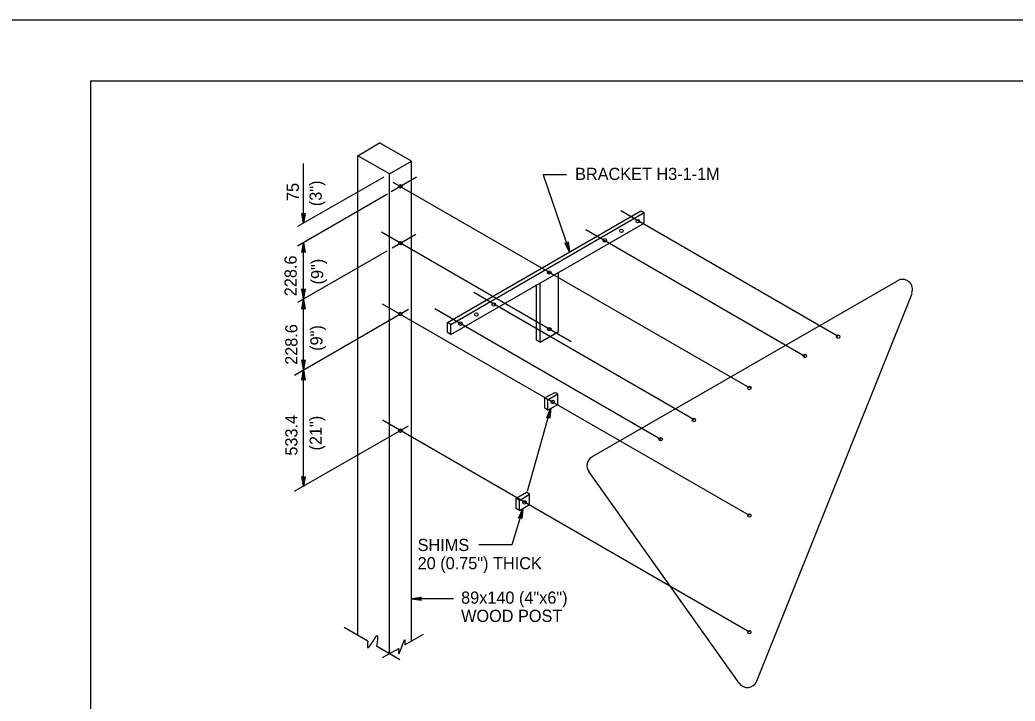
# Model space of a CAD drawing. Extents: x 649454 to 651200, y 295188 to 295782.
# Drawn here: x 650317.9 to 650563.3, y 295613.6 to 295781.6 of the extents above; entities that cross this region are included whole.
import ezdxf

# ---------------------------------------------------------------- set-up
doc = ezdxf.new("R2010")
doc.units = 0
for name, color, linetype in [('1', 7, 'Continuous'), ('2', 7, 'Continuous'), ('3', 7, 'Continuous'), ('PLT-BNDY', 7, 'Continuous')]:
    doc.layers.add(name, color=color, linetype=linetype)

msp = doc.modelspace()

# ---------------------------------------------------------------- linework, layer by layer
at = {"layer": '1'}
for q in [(651121.31, 295766.63), (650335.31, 295202.63)]:
    msp.add_line((650335.31, 295766.63), q, dxfattribs=at)
at = {"layer": '2'}
for points in [[(650452.69, 295743.39), (650446.94, 295743.39), (650453.44, 295724.39)], [(650452.94, 295726.77), (650452.81, 295726.52), (650453.44, 295724.39), (650452.94, 295726.77), (650453.06, 295726.89), (650453.44, 295724.39), (650452.56, 295726.52), (650452.44, 295726.52), (650453.44, 295724.39), (650452.31, 295726.64), (650452.44, 295726.52)], [(650447.94, 295683.64), (650448.19, 295683.64), (650448.81, 295685.89), (650447.94, 295683.64), (650447.81, 295683.52), (650448.81, 295685.89), (650448.31, 295683.64), (650448.44, 295683.52), (650448.81, 295685.89), (650448.56, 295683.39), (650448.44, 295683.52)], [(650440.94, 295658.89), (650441.19, 295658.89), (650441.94, 295661.02), (650440.94, 295658.89), (650440.81, 295658.77), (650441.94, 295661.02), (650441.44, 295658.89), (650441.56, 295658.77), (650441.94, 295661.02), (650441.69, 295658.64), (650441.56, 295658.77)], [(650416.81, 295638.52), (650416.69, 295638.77), (650414.44, 295638.89), (650416.81, 295638.52), (650416.94, 295638.52), (650414.44, 295638.89), (650416.69, 295639.02), (650416.81, 295639.14), (650414.44, 295638.89), (650416.94, 295639.27), (650416.81, 295639.14)], [(650424.81, 295638.89), (650414.44, 295638.89)]]:
    msp.add_lwpolyline(points, dxfattribs=at)
for centre, start, end in [((650535.54, 295715.15), 338.2171, 119.9923), ((650460.21, 295671.66), 119.9878, 215.3941), ((650497.3, 295619.47), 215.3991, 336.1301)]:
    msp.add_arc(centre, 2.49, start, end, dxfattribs=at)
at = {"layer": '3'}
for p, q in [((650401.19, 295748.14), (650406.56, 295751.27)), ((650414.44, 295746.77), (650406.56, 295751.27)), ((650401.19, 295629.77), (650401.19, 295748.14)), ((650409.06, 295743.64), (650401.19, 295748.14)), ((650387.81, 295731.52), (650387.81, 295746.21)), ((650409.06, 295743.64), (650414.44, 295746.77)), ((650414.44, 295628.52), (650414.44, 295746.77)), ((650409.06, 295625.39), (650409.06, 295743.64)), ((650386.44, 295730.77), (650407.69, 295742.89)), ((650409.44, 295739.27), (650415.69, 295742.89)), ((650497.81, 295690.89), (650409.94, 295741.52)), ((650386.31, 295725.89), (650408.56, 295738.77)), ((650411.69, 295740.52), (650411.69, 295740.52)), ((650423.31, 295707.02), (650471.06, 295734.52)), ((650424.19, 295706.52), (650471.81, 295734.14)), ((650519.69, 295703.52), (650466.06, 295734.52)), ((650469.69, 295734.02), (650469.69, 295734.02)), ((650471.06, 295734.52), (650471.81, 295734.14)), ((650471.81, 295731.52), (650471.81, 295734.14)), ((650424.19, 295704.02), (650471.81, 295731.52)), ((650471.81, 295731.52), (650471.81, 295731.52)), ((650453.81, 295702.27), (650407.06, 295729.27)), ((650409.69, 295725.39), (650415.56, 295728.77)), ((650511.44, 295698.64), (650457.44, 295729.89)), ((650387.81, 295712.77), (650387.81, 295726.77)), ((650411.69, 295726.52), (650411.69, 295726.52)), ((650386.44, 295712.02), (650408.44, 295724.64)), ((650445.94, 295719.27), (650445.94, 295719.27)), ((650447.44, 295719.89), (650447.44, 295719.89)), ((650450.69, 295704.77), (650450.69, 295719.39)), ((650441.94, 295716.77), (650441.94, 295716.77)), ((650443.19, 295717.64), (650443.19, 295717.64)), ((650444.69, 295718.39), (650444.69, 295718.39)), ((650445.31, 295702.64), (650445.31, 295716.39)), ((650446.19, 295702.14), (650446.19, 295716.77)), ((650458.94, 295673.89), (650534.31, 295717.27)), ((650484.19, 295683.02), (650429.81, 295714.39)), ((650436.31, 295713.64), (650436.31, 295713.64)), ((650437.81, 295714.39), (650437.81, 295714.39)), ((650439.19, 295715.27), (650439.19, 295715.27)), ((650440.56, 295716.02), (650440.56, 295716.02)), ((650448.44, 295715.14), (650448.44, 295715.14)), ((650499.56, 295618.39), (650537.94, 295714.14)), ((650387.81, 295695.39), (650387.81, 295712.77)), ((650497.81, 295659.39), (650407.31, 295711.52)), ((650432.31, 295711.27), (650432.31, 295711.27)), ((650433.69, 295712.14), (650433.69, 295712.14)), ((650435.06, 295712.89), (650435.06, 295712.89)), ((650385.56, 295694.02), (650413.69, 295710.27)), ((650475.94, 295678.14), (650420.19, 295710.39)), ((650428.19, 295708.89), (650428.19, 295708.89)), ((650429.56, 295709.77), (650429.56, 295709.77)), ((650430.44, 295709.02), (650430.44, 295709.02)), ((650430.94, 295710.52), (650430.94, 295710.52)), ((650424.19, 295706.52), (650423.31, 295707.02)), ((650423.31, 295704.52), (650423.31, 295707.02)), ((650424.19, 295704.02), (650424.19, 295706.52)), ((650424.19, 295706.52), (650424.19, 295706.52)), ((650425.44, 295707.39), (650425.44, 295707.39)), ((650426.94, 295708.14), (650426.94, 295708.14)), ((650424.19, 295704.02), (650423.31, 295704.52)), ((650446.19, 295702.14), (650450.69, 295704.77)), ((650448.44, 295705.27), (650448.44, 295705.27)), ((650446.19, 295702.14), (650445.31, 295702.64)), ((650387.81, 295666.52), (650387.81, 295694.02)), ((650447.31, 295688.39), (650449.81, 295689.77)), ((650448.06, 295687.89), (650450.56, 295689.39)), ((650450.56, 295689.39), (650449.81, 295689.77)), ((650450.56, 295686.77), (650450.56, 295689.39)), ((650448.06, 295687.89), (650447.31, 295688.39)), ((650447.31, 295685.89), (650447.31, 295688.39)), ((650448.06, 295685.39), (650448.06, 295687.89)), ((650448.06, 295685.39), (650450.56, 295686.77)), ((650448.06, 295685.39), (650447.31, 295685.89)), ((650497.81, 295630.64), (650407.31, 295682.89)), ((650385.56, 295665.39), (650413.69, 295681.52)), ((650495.31, 295618.02), (650458.19, 295670.27)), ((650440.31, 295663.64), (650442.81, 295665.14)), ((650441.06, 295663.14), (650443.56, 295664.64)), ((650443.56, 295664.64), (650442.81, 295665.14)), ((650443.56, 295662.14), (650443.56, 295664.64)), ((650441.06, 295663.14), (650440.31, 295663.64)), ((650440.31, 295661.14), (650440.31, 295663.64)), ((650441.06, 295660.64), (650441.06, 295663.14)), ((650441.06, 295660.64), (650443.56, 295662.14)), ((650441.94, 295661.02), (650439.18, 295652.16)), ((650441.06, 295660.64), (650440.31, 295661.14)), ((650439.18, 295652.16), (650431.08, 295652.16)), ((650403.69, 295628.39), (650397.81, 295631.77)), ((650412.81, 295627.52), (650417.44, 295630.14)), ((650411.56, 295623.77), (650405.81, 295627.14)), ((650407.31, 295624.39), (650411.31, 295626.64))]:
    msp.add_line(p, q, dxfattribs=at)
for points in [[(650388.19, 295733.77), (650387.94, 295733.77), (650387.81, 295731.52), (650388.19, 295733.77), (650388.19, 295733.89), (650387.81, 295731.52), (650387.69, 295733.77), (650387.56, 295733.77), (650387.81, 295731.52), (650387.44, 295733.89), (650387.56, 295733.77)], [(650387.56, 295724.39), (650387.69, 295724.52), (650387.81, 295726.77), (650387.56, 295724.39), (650387.44, 295724.27), (650387.81, 295726.77), (650387.94, 295724.52), (650388.06, 295724.39), (650387.81, 295726.77), (650388.19, 295724.27), (650388.06, 295724.39)], [(650388.19, 295715.14), (650387.94, 295715.02), (650387.81, 295712.77), (650388.19, 295715.14), (650388.19, 295715.27), (650387.81, 295712.77), (650387.69, 295715.02), (650387.56, 295715.14), (650387.81, 295712.77), (650387.44, 295715.27), (650387.56, 295715.14)], [(650387.56, 295710.39), (650387.69, 295710.52), (650387.81, 295712.77), (650387.56, 295710.39), (650387.44, 295710.27), (650387.81, 295712.77), (650387.94, 295710.52), (650388.06, 295710.39), (650387.81, 295712.77), (650388.19, 295710.27), (650388.06, 295710.39)], [(650388.19, 295697.64), (650387.94, 295697.64), (650387.81, 295695.39), (650388.19, 295697.64), (650388.19, 295697.77), (650387.81, 295695.39), (650387.69, 295697.64), (650387.56, 295697.64), (650387.81, 295695.39), (650387.44, 295697.77), (650387.56, 295697.64)], [(650387.56, 295692.89), (650387.69, 295693.02), (650387.81, 295695.39), (650387.56, 295692.89), (650387.44, 295692.77), (650387.81, 295695.39), (650387.94, 295693.02), (650388.06, 295692.89), (650387.81, 295695.39), (650388.19, 295692.77), (650388.06, 295692.89)], [(650443.06, 295665.39), (650448.81, 295685.89)], [(650388.19, 295668.89), (650387.94, 295668.77), (650387.81, 295666.52), (650388.19, 295668.89), (650388.19, 295669.02), (650387.81, 295666.52), (650387.69, 295668.77), (650387.56, 295668.89), (650387.81, 295666.52), (650387.44, 295669.02), (650387.56, 295668.89)]]:
    msp.add_lwpolyline(points, dxfattribs=at)
for centre in [(650411.7, 295740.57), (650470.3, 295731.98), (650466.24, 295729.62), (650411.7, 295726.56), (650462.14, 295727.25), (650448.45, 295719.35), (650434.76, 295711.45), (650411.7, 295709.1), (650430.45, 295708.96), (650426.55, 295706.71), (650448.45, 295705.34), (650519.7, 295703.49), (650511.5, 295698.75), (650497.81, 295690.85), (650449.3, 295687.4), (650484.12, 295682.95), (650411.7, 295680.34), (650475.91, 295678.21), (650442.33, 295662.65), (650497.81, 295659.39), (650497.81, 295630.62)]:
    msp.add_circle(centre, 0.428, dxfattribs=at)
for points in [[(650403.69, 295628.39), (650403.69, 295626.77), (650405.94, 295629.77), (650405.81, 295627.14)], [(650411.31, 295626.64), (650411.31, 295625.27), (650412.81, 295628.77), (650412.81, 295627.52)]]:
    msp.add_spline(points, degree=3, dxfattribs=at)
at = {"layer": 'PLT-BNDY'}
msp.add_lwpolyline([(650295.31, 295781.63), (651136.31, 295781.63), (651136.31, 295187.63), (650295.31, 295187.63)], close=True, dxfattribs=at)

# ---------------------------------------------------------------- texts
at = {"layer": '3'}
for s, p in [('BRACKET H3-1-1M', (650454.81, 295742.15)), ('SHIMS', (650415.97, 295650.64)), ('20 (0.75") THICK', (650415.97, 295646.14)), ('89x140 (4"x6")', (650426.69, 295637.65)), ('WOOD POST', (650426.69, 295633.15))]:
    msp.add_text(s, height=3, dxfattribs=at).set_placement(p)
for s, p in [('75', (650386.68, 295736.96)), ('(3")', (650392.32, 295735.69)), ('228.6', (650386.13, 295713.48)), ('(9")', (650392.68, 295716.39)), ('228.6', (650386.31, 295696.55)), ('(9")', (650392.5, 295700.01)), ('533.4', (650386.31, 295674.16)), ('(21")', (650392.32, 295675.44))]:
    msp.add_text(s, height=3, rotation=90, dxfattribs=at).set_placement(p)

doc.saveas('drawing.dxf')
